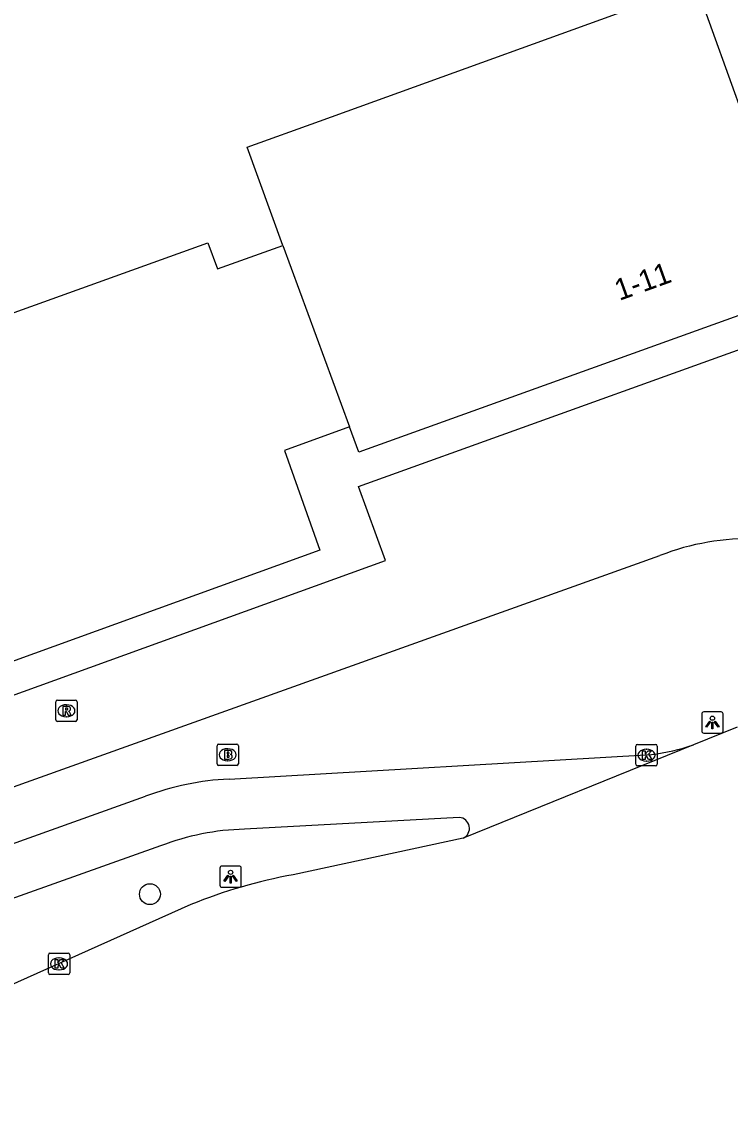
# Model space of a CAD drawing. Extents: x 160379 to 161131, y 383940 to 384849.
# Drawn here: x 160918.9 to 160952.1, y 383953.6 to 384004.7 of the extents above; entities that cross this region are included whole.
import ezdxf

# ---------------------------------------------------------------- set-up
doc = ezdxf.new("R2010")
doc.units = 0
for name, color, linetype in [('IMGEO_Boom', 7, 'Continuous'), ('IMGEO_Brandkraan', 7, 'Continuous'), ('IMGEO_Fietspad_open', 7, 'Continuous'), ('IMGEO_Groenvoorziening', 7, 'Continuous'), ('IMGEO_Kolk', 7, 'Continuous'), ('IMGEO_Lichtpunt', 7, 'Continuous'), ('IMGEO_Pand', 7, 'Continuous'), ('IMGEO_Pand_nummerreeks', 7, 'Continuous'), ('IMGEO_Rijbaan_lokaal_open', 7, 'Continuous'), ('IMGEO_Rioolput', 7, 'Continuous'), ('IMGEO_Voetpad_open', 7, 'Continuous')]:
    doc.layers.add(name, color=color, linetype=linetype)

msp = doc.modelspace()

# ---------------------------------------------------------------- linework, layer by layer
at = {"layer": 'IMGEO_Boom'}
msp.add_circle((160924.877, 383963.77), 0.489, dxfattribs=at)
at = {"layer": 'IMGEO_Brandkraan'}
for p, q in [((160928.02, 383969.876), (160928.02, 383970.728)), ((160928.095, 383970.802), (160928.947, 383970.802)), ((160928.508, 383970.582), (160928.533, 383970.582)), ((160929.021, 383970.728), (160929.021, 383969.876)), ((160928.531, 383970.022), (160928.506, 383970.022)), ((160928.947, 383969.802), (160928.095, 383969.802))]:
    msp.add_line(p, q, dxfattribs=at)
for points in [[(160928.02, 383969.876), (160928.02, 383970.728)], [(160928.095, 383970.802), (160928.947, 383970.802)], [(160928.368, 383970.502), (160928.368, 383970.102), (160928.581, 383970.102)], [(160928.599, 383970.502), (160928.368, 383970.502)], [(160929.021, 383970.728), (160929.021, 383969.876)], [(160928.547, 383970.421), (160928.493, 383970.421), (160928.493, 383970.345)], [(160928.493, 383970.345), (160928.546, 383970.345)], [(160928.555, 383970.269), (160928.493, 383970.269), (160928.493, 383970.188)], [(160928.493, 383970.188), (160928.555, 383970.188)], [(160928.947, 383969.802), (160928.095, 383969.802)]]:
    msp.add_lwpolyline(points, dxfattribs=at)
for centre, radius, start, end in [((160928.097, 383970.726), 0.0765, 91.552, 178.448), ((160928.097, 383970.726), 0.0765, 91.552, 178.448), ((160928.603, 383970.357), 0.145, 59.4692, 91.5367), ((160928.628, 383970.404), 0.0922, 285.5137, 58.1501), ((160928.945, 383970.726), 0.0765, 1.552, 88.448), ((160928.945, 383970.726), 0.0765, 1.552, 88.448), ((160928.548, 383970.383), 0.0379, 267.8285, 90.9355), ((160928.556, 383970.228), 0.0404, 269.8759, 90.5077), ((160928.587, 383970.353), 0.251, 268.6676, 293.5347), ((160928.633, 383970.212), 0.105, 301.3115, 78.989), ((160928.097, 383969.878), 0.0765, 181.552, 268.448), ((160928.097, 383969.878), 0.0765, 181.552, 268.448), ((160928.945, 383969.878), 0.0765, 271.552, 358.448), ((160928.945, 383969.878), 0.0765, 271.552, 358.448)]:
    msp.add_arc(centre, radius, start, end, dxfattribs=at)
for centre, major_axis, ratio, start_param, end_param in [((160928.507, 383970.302), (-0.387, 0.002), 0.722429, 4.712389, 7.853982), ((160928.532, 383970.302), (-0.39, 0.002), 0.717154, 1.570796, 4.712389)]:
    msp.add_ellipse(centre, major_axis=major_axis, ratio=ratio, start_param=start_param, end_param=end_param, dxfattribs=at)
at = {"layer": 'IMGEO_Fietspad_open'}
for points in [[(160928.583, 383969.165), (160948.379, 383970.31)], [(160899.709, 383959.43), (160924.669, 383968.355)], [(160939.37, 383967.365), (160929.306, 383966.813)], [(160925.376, 383966.027), (160906.731, 383959.392), (160902.329, 383957.759)]]:
    msp.add_lwpolyline(points, dxfattribs=at)
for centre, radius, start, end in [((160947.206, 383979.703), 9.466, 277.1211, 289.3371), ((160929.219, 383956.23), 12.95, 92.8151, 110.5695), ((160939.335, 383966.852), 0.514, 296.1295, 86.0602), ((160929.555, 383955.352), 11.464, 91.2427, 111.3772)]:
    msp.add_arc(centre, radius, start, end, dxfattribs=at)
at = {"layer": 'IMGEO_Groenvoorziening'}
msp.add_lwpolyline([(160912.378, 383970.889), (160935.911, 383979.399), (160934.651, 383982.882), (160958.879, 383991.594)], dxfattribs=at)
at = {"layer": 'IMGEO_Kolk'}
for p, q in [((160947.642, 383969.856), (160947.642, 383970.708)), ((160947.717, 383970.782), (160948.569, 383970.782)), ((160948.13, 383970.562), (160948.155, 383970.562)), ((160948.643, 383970.708), (160948.643, 383969.856)), ((160948.153, 383970.002), (160948.128, 383970.002)), ((160948.569, 383969.782), (160947.717, 383969.782)), ((160920.119, 383960.076), (160920.119, 383960.928)), ((160920.194, 383961.002), (160921.046, 383961.002)), ((160920.607, 383960.782), (160920.632, 383960.782)), ((160921.12, 383960.928), (160921.12, 383960.076)), ((160921.046, 383960.002), (160920.194, 383960.002)), ((160920.63, 383960.222), (160920.605, 383960.222))]:
    msp.add_line(p, q, dxfattribs=at)
for points in [[(160947.642, 383969.856), (160947.642, 383970.708)], [(160947.717, 383970.782), (160948.569, 383970.782)], [(160947.963, 383970.482), (160948.086, 383970.482), (160948.086, 383970.331), (160948.216, 383970.482), (160948.38, 383970.482), (160948.234, 383970.331), (160948.387, 383970.082), (160948.235, 383970.082), (160948.15, 383970.246), (160948.086, 383970.179), (160948.086, 383970.082), (160947.963, 383970.082), (160947.963, 383970.482)], [(160948.643, 383970.708), (160948.643, 383969.856)], [(160948.569, 383969.782), (160947.717, 383969.782)], [(160920.119, 383960.076), (160920.119, 383960.928)], [(160920.194, 383961.002), (160921.046, 383961.002)], [(160921.12, 383960.928), (160921.12, 383960.076)], [(160920.44, 383960.702), (160920.563, 383960.702), (160920.563, 383960.551), (160920.693, 383960.702), (160920.857, 383960.702), (160920.711, 383960.551), (160920.864, 383960.302), (160920.712, 383960.302), (160920.627, 383960.466), (160920.563, 383960.399), (160920.563, 383960.302), (160920.44, 383960.302), (160920.44, 383960.702)], [(160921.046, 383960.002), (160920.194, 383960.002)]]:
    msp.add_lwpolyline(points, dxfattribs=at)
for centre, start, end in [((160947.719, 383970.706), 91.552, 178.448), ((160947.719, 383970.706), 91.552, 178.448), ((160948.567, 383970.706), 1.552, 88.448), ((160948.567, 383970.706), 1.552, 88.448), ((160947.719, 383969.858), 181.552, 268.448), ((160947.719, 383969.858), 181.552, 268.448), ((160948.567, 383969.858), 271.552, 358.448), ((160948.567, 383969.858), 271.552, 358.448), ((160920.196, 383960.926), 91.552, 178.448), ((160920.196, 383960.926), 91.552, 178.448), ((160921.044, 383960.926), 1.552, 88.448), ((160921.044, 383960.926), 1.552, 88.448), ((160920.196, 383960.078), 181.552, 268.448), ((160920.196, 383960.078), 181.552, 268.448), ((160921.044, 383960.078), 271.552, 358.448), ((160921.044, 383960.078), 271.552, 358.448)]:
    msp.add_arc(centre, 0.0765, start, end, dxfattribs=at)
for centre, major_axis, ratio, start_param, end_param in [((160948.129, 383970.282), (-0.387, 0.002), 0.722429, 4.712389, 7.853982), ((160948.154, 383970.282), (-0.39, 0.002), 0.717154, 1.570796, 4.712389), ((160920.606, 383960.502), (-0.387, 0.002), 0.722429, 4.712389, 7.853982), ((160920.631, 383960.502), (-0.39, 0.002), 0.717154, 1.570796, 4.712389)]:
    msp.add_ellipse(centre, major_axis=major_axis, ratio=ratio, start_param=start_param, end_param=end_param, dxfattribs=at)
at = {"layer": 'IMGEO_Lichtpunt'}
for p, q in [((160950.733, 383972.217), (160950.733, 383971.41)), ((160950.733, 383972.217), (160950.733, 383971.41)), ((160951.635, 383972.312), (160950.827, 383972.312)), ((160951.635, 383972.312), (160950.827, 383972.312)), ((160951.729, 383971.41), (160951.729, 383972.217)), ((160951.729, 383971.41), (160951.729, 383972.217)), ((160950.827, 383971.316), (160951.635, 383971.316)), ((160950.827, 383971.316), (160951.635, 383971.316)), ((160928.157, 383964.993), (160928.157, 383964.186)), ((160928.157, 383964.993), (160928.157, 383964.186)), ((160929.059, 383965.088), (160928.251, 383965.088)), ((160929.059, 383965.088), (160928.251, 383965.088)), ((160929.153, 383964.186), (160929.153, 383964.993)), ((160929.153, 383964.186), (160929.153, 383964.993)), ((160928.251, 383964.092), (160929.059, 383964.092)), ((160928.251, 383964.092), (160929.059, 383964.092))]:
    msp.add_line(p, q, dxfattribs=at)
for points in [[(160951.107, 383971.881), (160951.146, 383971.853), (160950.958, 383971.591), (160950.92, 383971.618), (160951.107, 383971.881)], [(160951.209, 383971.833), (160951.256, 383971.833), (160951.256, 383971.511), (160951.209, 383971.511), (160951.209, 383971.833)], [(160951.319, 383971.853), (160951.357, 383971.88), (160951.544, 383971.618), (160951.505, 383971.59), (160951.319, 383971.853)], [(160928.531, 383964.657), (160928.57, 383964.629), (160928.382, 383964.367), (160928.344, 383964.394), (160928.531, 383964.657)], [(160928.633, 383964.609), (160928.68, 383964.609), (160928.68, 383964.287), (160928.633, 383964.287), (160928.633, 383964.609)], [(160928.743, 383964.629), (160928.781, 383964.656), (160928.968, 383964.394), (160928.929, 383964.366), (160928.743, 383964.629)]]:
    msp.add_lwpolyline(points, dxfattribs=at)
for centre in [(160951.232, 383972.015), (160928.656, 383964.791)]:
    msp.add_circle(centre, 0.0994, dxfattribs=at)
for centre, start, end in [((160950.827, 383972.217), 90, 180), ((160950.827, 383972.217), 90, 180), ((160951.635, 383972.217), 0, 90), ((160951.635, 383972.217), 0, 90), ((160950.827, 383971.41), 180, 270), ((160950.827, 383971.41), 180, 270), ((160951.635, 383971.41), 270, 0), ((160951.635, 383971.41), 270, 360), ((160928.251, 383964.993), 90, 180), ((160928.251, 383964.993), 90, 180), ((160929.059, 383964.993), 0, 90), ((160929.059, 383964.993), 0, 90), ((160928.251, 383964.186), 180, 270), ((160928.251, 383964.186), 180, 270), ((160929.059, 383964.186), 270, 0), ((160929.059, 383964.186), 270, 360)]:
    msp.add_arc(centre, 0.0946, start, end, dxfattribs=at)
at = {"layer": 'IMGEO_Pand'}
for points in [[(160890.019, 383979.804), (160878.218, 383998.754), (160879.312, 383999.528), (160877.59, 384002.284), (160873.484, 383999.72), (160856.296, 384027.247), (160864.594, 384032.426), (160866.099, 384029.947), (160870.79, 384032.876), (160886.364, 384007.76), (160885.303, 384007.097), (160887.007, 384004.357), (160891.169, 384006.921), (160895.48, 384000), (160901.823, 383989.818), (160904.071, 383991.206), (160907.739, 383989.957), (160908.639, 383987.488), (160927.586, 383994.29), (160928.046, 383993.07), (160931.098, 383994.168)], [(160931.098, 383994.168), (160929.431, 383998.775), (160932.817, 384000), (160950.451, 384006.379), (160952.748, 384000)], [(160975.611, 383999.256), (160958.376, 383993.007), (160934.661, 383984.48), (160934.233, 383985.666)], [(160931.098, 383994.168), (160934.233, 383985.666)], [(160934.233, 383985.666), (160931.177, 383984.562), (160932.841, 383979.884), (160911.861, 383972.297)]]:
    msp.add_lwpolyline(points, dxfattribs=at)
at = {"layer": 'IMGEO_Rijbaan_lokaal_open'}
for points in [[(160952.387, 383971.601), (160950.34, 383970.771)], [(160950.34, 383970.771), (160939.561, 383966.391)], [(160939.561, 383966.391), (160931.592, 383964.679)], [(160926.798, 383963.284), (160905.27, 383953.642)]]:
    msp.add_lwpolyline(points, dxfattribs=at)
msp.add_arc((160936.116, 383940.198), 24.896, 100.4694, 111.9794, dxfattribs=at)
at = {"layer": 'IMGEO_Rioolput'}
for p, q in [((160920.464, 383971.938), (160920.464, 383972.79)), ((160920.539, 383972.864), (160921.391, 383972.864)), ((160920.952, 383972.644), (160920.977, 383972.644)), ((160921.465, 383972.79), (160921.465, 383971.938)), ((160920.975, 383972.084), (160920.95, 383972.084)), ((160921.391, 383971.864), (160920.539, 383971.864))]:
    msp.add_line(p, q, dxfattribs=at)
for points in [[(160920.464, 383971.938), (160920.464, 383972.79)], [(160920.539, 383972.864), (160921.391, 383972.864)], [(160921.053, 383972.562), (160920.801, 383972.564), (160920.801, 383972.164)], [(160921.465, 383972.79), (160921.465, 383971.938)], [(160920.801, 383972.164), (160920.925, 383972.164), (160920.925, 383972.326), (160920.936, 383972.326)], [(160920.979, 383972.483), (160920.925, 383972.483), (160920.925, 383972.402)], [(160920.925, 383972.402), (160920.977, 383972.402)], [(160920.983, 383972.297), (160921.054, 383972.164), (160921.194, 383972.164), (160921.129, 383972.29)], [(160921.391, 383971.864), (160920.539, 383971.864)]]:
    msp.add_lwpolyline(points, dxfattribs=at)
for centre, radius, start, end in [((160920.541, 383972.788), 0.0765, 91.552, 178.448), ((160920.541, 383972.788), 0.0765, 91.552, 178.448), ((160921.052, 383972.452), 0.109, 350.3612, 89.416), ((160921.389, 383972.788), 0.0765, 1.552, 88.448), ((160921.389, 383972.788), 0.0765, 1.552, 88.448), ((160920.935, 383972.273), 0.0533, 26.0293, 88.6989), ((160920.961, 383972.591), 0.19, 274.7715, 282.9687), ((160920.985, 383972.387), 0.0964, 77.0061, 93.1865), ((160920.999, 383972.444), 0.0378, 276.6634, 79.6772), ((160921.05, 383972.452), 0.112, 277.5842, 350.9817), ((160921.034, 383972.237), 0.108, 29.5134, 73.7905), ((160920.541, 383971.94), 0.0765, 181.552, 268.448), ((160920.541, 383971.94), 0.0765, 181.552, 268.448), ((160921.389, 383971.94), 0.0765, 271.552, 358.448), ((160921.389, 383971.94), 0.0765, 271.552, 358.448)]:
    msp.add_arc(centre, radius, start, end, dxfattribs=at)
for centre, major_axis, ratio, start_param, end_param in [((160920.951, 383972.364), (-0.387, 0.002), 0.722429, 4.712389, 7.853982), ((160920.976, 383972.364), (-0.39, 0.002), 0.717154, 1.570796, 4.712389)]:
    msp.add_ellipse(centre, major_axis=major_axis, ratio=ratio, start_param=start_param, end_param=end_param, dxfattribs=at)
at = {"layer": 'IMGEO_Voetpad_open'}
msp.add_lwpolyline([(160913.618, 383967.508), (160913.799, 383967.125), (160948.774, 383979.638)], dxfattribs=at)
msp.add_arc((160952.946, 383968.998), 11.429, 88.0118, 111.4127, dxfattribs=at)

# ---------------------------------------------------------------- texts
at = {"layer": 'IMGEO_Pand_nummerreeks'}
msp.add_text('1-11', height=1, rotation=19.8608, dxfattribs=at).set_placement((160946.87, 383991.57))

doc.saveas('drawing.dxf')
